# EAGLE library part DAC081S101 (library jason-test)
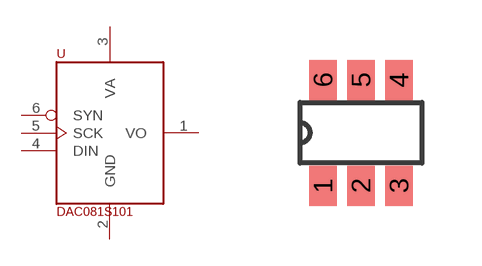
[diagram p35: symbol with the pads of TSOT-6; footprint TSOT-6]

Designator prefix -

## DAC081S101  [TSOT-6]
1  VO  out
2  GND  pwr
3  VA  pwr
4  DIN  in
5  SCK  in
6  SYN  in

## Footprint TSOT-6 (pad centres in mm)
smd 0.69 x 1: 1 -0.95,-1.325; 2 0,-1.325; 3 0.95,-1.325; 4 0.95,1.325; 5 0,1.325; 6 -0.95,1.325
